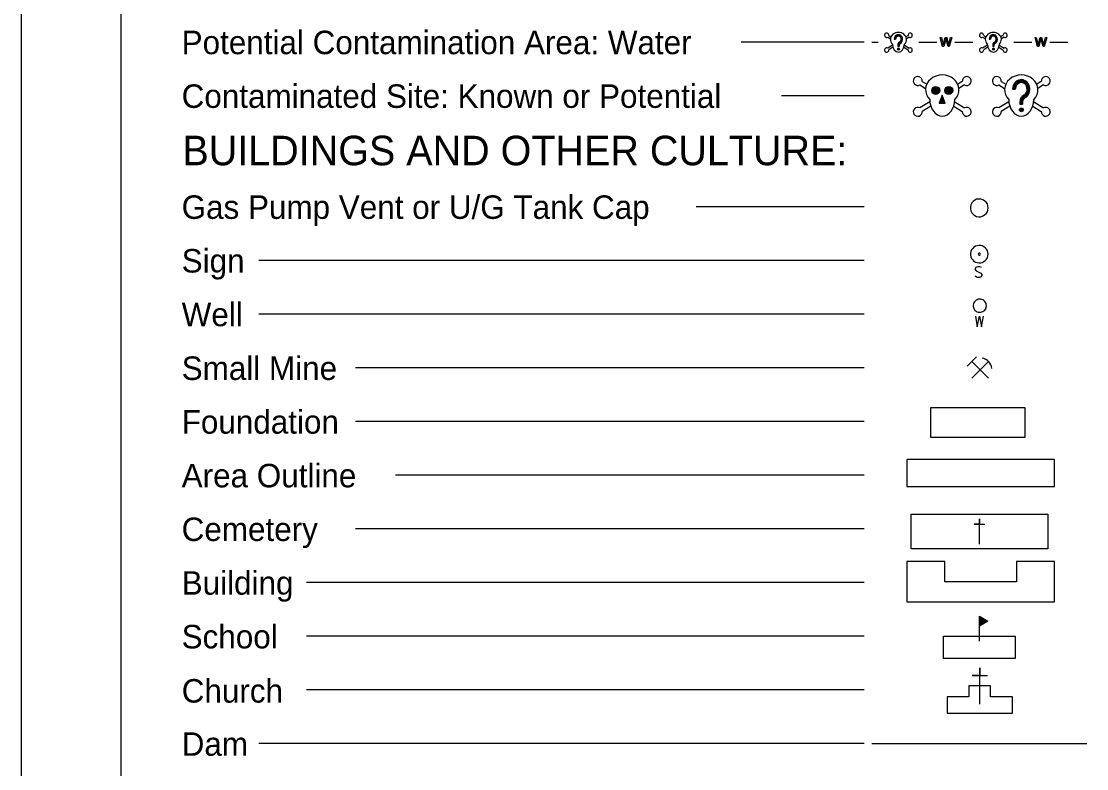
# Model space of a CAD drawing. Extents: x -0.53 to 3.34, y -0.27 to 4.33.
# Drawn here: x 0.217 to 0.885, y 2.956 to 3.424 of the extents above; entities that cross this region are included whole.
import ezdxf

# ---------------------------------------------------------------- set-up
doc = ezdxf.new("R2010")
doc.units = 0
for name, color, linetype in [('Sheet_Plan', 7, 'Continuous'), ('Sheet_Symbology', 7, 'Continuous'), ('z - Construction', 7, 'Continuous')]:
    doc.layers.add(name, color=color, linetype=linetype)

msp = doc.modelspace()

# ---------------------------------------------------------------- linework, layer by layer
at = {"layer": 'Sheet_Plan'}
msp.add_line((0.2799, 2.55761), (0.2799, 4.26594), dxfattribs=at)
at = {"layer": 'Sheet_Symbology'}
for p, q in [((0.7452, 3.41079), (0.66821, 3.41079)), ((0.75003, 3.41081), (0.75392, 3.41081)), ((0.75995, 3.41387), (0.76164, 3.41281)), ((0.76062, 3.41494), (0.76199, 3.41408)), ((0.76406, 3.41257), (0.76486, 3.41257)), ((0.76665, 3.41081), (0.76665, 3.41081)), ((0.77269, 3.41494), (0.77132, 3.41408)), ((0.77336, 3.41387), (0.77167, 3.41281)), ((0.77939, 3.41081), (0.79071, 3.41081)), ((0.80204, 3.41081), (0.81336, 3.41081)), ((0.81939, 3.41387), (0.82109, 3.41281)), ((0.82006, 3.41494), (0.82144, 3.41408)), ((0.8235, 3.41257), (0.8243, 3.41257)), ((0.8261, 3.41081), (0.8261, 3.41081)), ((0.83213, 3.41494), (0.83076, 3.41408)), ((0.8328, 3.41387), (0.83111, 3.41281)), ((0.83884, 3.41081), (0.85016, 3.41081)), ((0.86148, 3.41081), (0.8728, 3.41081)), ((0.76291, 3.40879), (0.75995, 3.40693)), ((0.76319, 3.40748), (0.76062, 3.40586)), ((0.76625, 3.40878), (0.76625, 3.40808)), ((0.76625, 3.40808), (0.76706, 3.40808)), ((0.76637, 3.40878), (0.76637, 3.40808)), ((0.76648, 3.40878), (0.76648, 3.40808)), ((0.7666, 3.40878), (0.7666, 3.40808)), ((0.76671, 3.40878), (0.76671, 3.40808)), ((0.76683, 3.40878), (0.76683, 3.40808)), ((0.76694, 3.40878), (0.76694, 3.40808)), ((0.76706, 3.40878), (0.76706, 3.40808)), ((0.77012, 3.40748), (0.77269, 3.40586)), ((0.7704, 3.40879), (0.77336, 3.40693)), ((0.82235, 3.40879), (0.81939, 3.40693)), ((0.82264, 3.40748), (0.82006, 3.40586)), ((0.8257, 3.40878), (0.8257, 3.40808)), ((0.8257, 3.40808), (0.8265, 3.40808)), ((0.82581, 3.40878), (0.82581, 3.40808)), ((0.82593, 3.40878), (0.82593, 3.40808)), ((0.82604, 3.40878), (0.82604, 3.40808)), ((0.82616, 3.40878), (0.82616, 3.40808)), ((0.82627, 3.40878), (0.82627, 3.40808)), ((0.82638, 3.40878), (0.82638, 3.40808)), ((0.8265, 3.40878), (0.8265, 3.40808)), ((0.82956, 3.40748), (0.83213, 3.40586)), ((0.82984, 3.40879), (0.8328, 3.40693)), ((0.78016, 3.38395), (0.78368, 3.38173)), ((0.78155, 3.38617), (0.78441, 3.38438)), ((0.80665, 3.38617), (0.8038, 3.38438)), ((0.80805, 3.38395), (0.80452, 3.38173)), ((0.82964, 3.38395), (0.83317, 3.38173)), ((0.83104, 3.38617), (0.83389, 3.38438)), ((0.85614, 3.38617), (0.85328, 3.38438)), ((0.85753, 3.38395), (0.85401, 3.38173)), ((0.7452, 3.37716), (0.69334, 3.37716)), ((0.7941, 3.37673), (0.7941, 3.37673)), ((0.83819, 3.38125), (0.83985, 3.38125)), ((0.84359, 3.37759), (0.84359, 3.37759)), ((0.78631, 3.37339), (0.78016, 3.36952)), ((0.78691, 3.37066), (0.78155, 3.3673)), ((0.8013, 3.37066), (0.80665, 3.3673)), ((0.80189, 3.37339), (0.80805, 3.36952)), ((0.8358, 3.37339), (0.82964, 3.36952)), ((0.83639, 3.37066), (0.83104, 3.3673)), ((0.84275, 3.37337), (0.84275, 3.3719)), ((0.84275, 3.3719), (0.84442, 3.3719)), ((0.84299, 3.37337), (0.84299, 3.3719)), ((0.84323, 3.37337), (0.84323, 3.3719)), ((0.84347, 3.37337), (0.84347, 3.3719)), ((0.84371, 3.37337), (0.84371, 3.3719)), ((0.84395, 3.37337), (0.84395, 3.3719)), ((0.84418, 3.37337), (0.84418, 3.3719)), ((0.84442, 3.37337), (0.84442, 3.3719)), ((0.85079, 3.37066), (0.85614, 3.3673)), ((0.85138, 3.37339), (0.85753, 3.36952)), ((0.7452, 3.30764), (0.63995, 3.30764)), ((0.7452, 3.27401), (0.36613, 3.27401)), ((0.7452, 3.24038), (0.36613, 3.24038)), ((0.81265, 3.21071), (0.80961, 3.20767)), ((0.81265, 3.20025), (0.82312, 3.21071)), ((0.7452, 3.20674), (0.42667, 3.20674)), ((0.81789, 3.20548), (0.81729, 3.20607)), ((0.81789, 3.20548), (0.82312, 3.20025)), ((0.78688, 3.18192), (0.84573, 3.18192)), ((0.78688, 3.16311), (0.78688, 3.18192)), ((0.84573, 3.18192), (0.84573, 3.16311)), ((0.7452, 3.17311), (0.42667, 3.17311)), ((0.84573, 3.16311), (0.78688, 3.16311)), ((0.86436, 3.14924), (0.77187, 3.14924)), ((0.77187, 3.14924), (0.77187, 3.13242)), ((0.86436, 3.13242), (0.86436, 3.14924)), ((0.7452, 3.13948), (0.45181, 3.13948)), ((0.77187, 3.13242), (0.86436, 3.13242)), ((0.77465, 3.11497), (0.86017, 3.11497)), ((0.77465, 3.09345), (0.77465, 3.11497)), ((0.86017, 3.11497), (0.86017, 3.09345)), ((0.7452, 3.10585), (0.42667, 3.10585)), ((0.86017, 3.09345), (0.77465, 3.09345)), ((0.79569, 3.0854), (0.77187, 3.0854)), ((0.77187, 3.0854), (0.77187, 3.06018)), ((0.79569, 3.07279), (0.79569, 3.0854)), ((0.86436, 3.0854), (0.84054, 3.0854)), ((0.84054, 3.0854), (0.84054, 3.07279)), ((0.86436, 3.06018), (0.86436, 3.0854)), ((0.7452, 3.07222), (0.39592, 3.07222)), ((0.84054, 3.07279), (0.79569, 3.07279)), ((0.77187, 3.06018), (0.86436, 3.06018)), ((0.7452, 3.03859), (0.39592, 3.03859)), ((0.79487, 3.03859), (0.83981, 3.03859)), ((0.79487, 3.02463), (0.79487, 3.03859)), ((0.83981, 3.03859), (0.83981, 3.02463)), ((0.83981, 3.02463), (0.79487, 3.02463)), ((0.7452, 3.00496), (0.39592, 3.00496)), ((0.82438, 3.00746), (0.81076, 3.00746)), ((0.81076, 3.00746), (0.81076, 3.00067)), ((0.82438, 3.00067), (0.82438, 3.00746)), ((0.81076, 3.00067), (0.79714, 3.00067)), ((0.79714, 3.00067), (0.79714, 2.99043)), ((0.838, 3.00067), (0.82438, 3.00067)), ((0.838, 2.99043), (0.838, 3.00067)), ((0.79714, 2.99043), (0.838, 2.99043)), ((0.7452, 2.97133), (0.36613, 2.97133)), ((0.75003, 2.97133), (0.88456, 2.97133))]:
    msp.add_line(p, q, dxfattribs=at)
for points in [[(0.79625, 3.4123), (0.79506, 3.40798), (0.79429, 3.40798), (0.79278, 3.41364), (0.79355, 3.41364), (0.79441, 3.40993)], [(0.79491, 3.40982), (0.79599, 3.41364), (0.79689, 3.41364), (0.7977, 3.41078)], [(0.79842, 3.41001), (0.79931, 3.41364), (0.80006, 3.41364), (0.79852, 3.40798), (0.79779, 3.40798), (0.7966, 3.4123)], [(0.85569, 3.4123), (0.8545, 3.40798), (0.85373, 3.40798), (0.85223, 3.41364), (0.853, 3.41364), (0.85386, 3.40993)], [(0.85435, 3.40982), (0.85543, 3.41364), (0.85633, 3.41364), (0.85715, 3.41078)], [(0.85787, 3.41001), (0.85875, 3.41364), (0.85951, 3.41364), (0.85796, 3.40798), (0.85723, 3.40798), (0.85604, 3.4123)], [(0.82294, 3.30692), (0.82264, 3.30826), (0.82234, 3.30945), (0.8216, 3.3105), (0.82055, 3.31139), (0.81951, 3.31199), (0.81832, 3.31244), (0.81697, 3.31244), (0.81563, 3.31229), (0.81444, 3.31169), (0.8134, 3.31095), (0.81266, 3.31005), (0.81206, 3.30886), (0.81176, 3.30752), (0.81176, 3.30633), (0.81206, 3.30499), (0.81266, 3.3038), (0.8134, 3.3029), (0.81444, 3.30216), (0.81563, 3.30156), (0.81697, 3.30141), (0.81832, 3.30141), (0.81951, 3.30186), (0.82055, 3.30246), (0.8216, 3.30335), (0.82234, 3.30439), (0.82264, 3.30558), (0.82294, 3.30692)], [(0.82278, 3.27791), (0.82267, 3.279), (0.82234, 3.2801), (0.82179, 3.28108), (0.82103, 3.28185), (0.82016, 3.2825), (0.81917, 3.28305), (0.81819, 3.28327), (0.81699, 3.28337), (0.8159, 3.28316), (0.81491, 3.28283), (0.81393, 3.28228), (0.81316, 3.28152), (0.81251, 3.28054), (0.81207, 3.27955), (0.81185, 3.27846), (0.81185, 3.27737), (0.81207, 3.27627), (0.81251, 3.27529), (0.81316, 3.27431), (0.81393, 3.27354), (0.81491, 3.273), (0.8159, 3.27267), (0.81699, 3.27245), (0.81819, 3.27256), (0.81917, 3.27278), (0.82016, 3.27332), (0.82103, 3.27398), (0.82179, 3.27475), (0.82234, 3.27573), (0.82267, 3.27682), (0.82278, 3.27791)], [(0.81754, 3.27857), (0.81721, 3.27857), (0.81688, 3.27835), (0.81666, 3.27802), (0.81677, 3.27769), (0.81699, 3.27737), (0.81732, 3.27726), (0.81764, 3.27737), (0.81786, 3.27759), (0.81797, 3.27802), (0.81786, 3.27835), (0.81754, 3.27857)], [(0.8186, 3.26949), (0.81754, 3.26997), (0.81632, 3.26997), (0.81521, 3.26949), (0.81473, 3.26865), (0.81473, 3.26833), (0.81526, 3.26754), (0.81833, 3.26595), (0.81886, 3.2652), (0.81881, 3.26457), (0.81833, 3.26372), (0.81743, 3.26325), (0.81616, 3.26325), (0.81558, 3.26346), (0.81473, 3.26404)], [(0.82177, 3.2456), (0.82164, 3.24633), (0.82151, 3.24706), (0.82117, 3.24772), (0.82071, 3.24832), (0.82018, 3.24885), (0.81958, 3.24925), (0.81886, 3.24951), (0.81813, 3.24971), (0.8174, 3.24971), (0.81667, 3.24964), (0.81594, 3.24938), (0.81535, 3.24905), (0.81475, 3.24858), (0.81422, 3.24805), (0.81389, 3.24739), (0.81363, 3.24673), (0.81349, 3.246), (0.81349, 3.24521), (0.81363, 3.24448), (0.81389, 3.24381), (0.81422, 3.24316), (0.81475, 3.24262), (0.81535, 3.24216), (0.81594, 3.24183), (0.81667, 3.24156), (0.8174, 3.2415), (0.81813, 3.2415), (0.81886, 3.2417), (0.81958, 3.24196), (0.82018, 3.24236), (0.82071, 3.24289), (0.82117, 3.24348), (0.82151, 3.24415), (0.82164, 3.24488), (0.82177, 3.2456)], [(0.8149, 3.23911), (0.81596, 3.23239), (0.81733, 3.23911), (0.81871, 3.23239), (0.81988, 3.23911)], [(0.81789, 3.20548), (0.81265, 3.21071), (0.81561, 3.21366)], [(0.82523, 3.20641), (0.82498, 3.20759), (0.82455, 3.20869), (0.82396, 3.2097), (0.8232, 3.21054), (0.82236, 3.21139), (0.82135, 3.21198), (0.82025, 3.21248), (0.81915, 3.21274)], [(0.81744, 3.09635), (0.81744, 3.11211), (0.81744, 3.10876), (0.81409, 3.10876), (0.82079, 3.10876)], [(0.8174, 3.03546), (0.8174, 3.05122), (0.82267, 3.04812), (0.8174, 3.04502), (0.81771, 3.04551), (0.81771, 3.05079), (0.82205, 3.04806), (0.81802, 3.0457), (0.81808, 3.05029), (0.82156, 3.04806), (0.81839, 3.04626), (0.81839, 3.04973), (0.821, 3.04806), (0.81876, 3.04681), (0.81876, 3.04917), (0.82044, 3.04812), (0.81908, 3.04731), (0.81908, 3.04861), (0.81994, 3.04812), (0.81939, 3.04781), (0.81932, 3.04818), (0.81951, 3.04812)], [(0.81757, 2.99611), (0.81757, 3.01881), (0.81757, 3.01398), (0.81274, 3.01398), (0.8224, 3.01398)]]:
    msp.add_lwpolyline(points, dxfattribs=at)
for points in [[(0.7941, 3.37759), (0.79226, 3.37255), (0.79595, 3.37255)], [(0.7941, 3.37673), (0.79268, 3.37285), (0.79553, 3.37285)], [(0.7941, 3.37588), (0.7931, 3.37314), (0.79511, 3.37314)], [(0.7941, 3.37502), (0.79352, 3.37343), (0.79468, 3.37343)], [(0.7941, 3.37417), (0.79394, 3.37373), (0.79426, 3.37373)]]:
    msp.add_lwpolyline(points, close=True, dxfattribs=at)
for centre, radius in [((0.76668, 3.40633), 0.000573), ((0.76668, 3.40633), 0.000446), ((0.76668, 3.40633), 0.000316), ((0.76668, 3.40633), 0.000188), ((0.76668, 3.40633), 0.0000611), ((0.82613, 3.40633), 0.000573), ((0.82613, 3.40633), 0.000446), ((0.82613, 3.40633), 0.000316), ((0.82613, 3.40633), 0.000188), ((0.82613, 3.40633), 0.0000611), ((0.79005, 3.38045), 0.0025), ((0.79005, 3.38045), 0.0022), ((0.79816, 3.38045), 0.0025), ((0.79816, 3.38045), 0.0022), ((0.79005, 3.38045), 0.00191), ((0.79005, 3.38045), 0.00161), ((0.79005, 3.38045), 0.00132), ((0.79005, 3.38045), 0.00102), ((0.79005, 3.38045), 0.00073), ((0.79005, 3.38045), 0.000435), ((0.79005, 3.38045), 0.000141), ((0.79816, 3.38045), 0.00191), ((0.79816, 3.38045), 0.00161), ((0.79816, 3.38045), 0.00132), ((0.79816, 3.38045), 0.00102), ((0.79816, 3.38045), 0.00073), ((0.79816, 3.38045), 0.000435), ((0.79816, 3.38045), 0.000141), ((0.84365, 3.36828), 0.00119), ((0.84365, 3.36828), 0.000927), ((0.84365, 3.36828), 0.000657), ((0.84365, 3.36828), 0.000392), ((0.84365, 3.36828), 0.000127)]:
    msp.add_circle(centre, radius, dxfattribs=at)
for centre, radius, start, end in [((0.75928, 3.41504), 0.00134, 355.89762, 299.80617), ((0.77403, 3.41504), 0.00134, 240.19383, 184.10238), ((0.81872, 3.41504), 0.00134, 355.89762, 299.80617), ((0.83347, 3.41504), 0.00134, 240.19383, 184.10238), ((0.75928, 3.40577), 0.00134, 60.19383, 4.10238), ((0.77403, 3.40577), 0.00134, 175.89762, 119.80617), ((0.81872, 3.40577), 0.00134, 60.19383, 4.10238), ((0.83347, 3.40577), 0.00134, 175.89762, 119.80617), ((0.77877, 3.38637), 0.00279, 355.89762, 299.80617), ((0.80943, 3.38637), 0.00279, 240.19383, 184.10238), ((0.82826, 3.38637), 0.00279, 355.89762, 299.80617), ((0.85892, 3.38637), 0.00279, 240.19383, 184.10238), ((0.77877, 3.3671), 0.00279, 60.19383, 4.10238), ((0.80943, 3.3671), 0.00279, 175.89762, 119.80617), ((0.82826, 3.3671), 0.00279, 60.19383, 4.10238), ((0.85892, 3.3671), 0.00279, 175.89762, 119.80617)]:
    msp.add_arc(centre, radius, start, end, dxfattribs=at)
for centre, major_axis, ratio, start_param, end_param in [((0.76665, 3.4124), (0.00503, 0), 0.885014, 5.564242, 10.143721), ((0.8261, 3.4124), (0.00503, 0), 0.885014, 5.564242, 10.143721), ((0.76665, 3.40952), (0, -0.00503), 0.752542, 4.722735, 7.843636), ((0.76665, 3.41257), (0, 0.00289), 0.9, 3.567618, 7.853982), ((0.76665, 3.41257), (0, 0.00276), 0.9, 3.567618, 7.853982), ((0.76665, 3.41257), (0, 0.00263), 0.9, 3.567618, 7.853982), ((0.76665, 3.41257), (0, 0.00251), 0.9, 3.567618, 7.853982), ((0.76665, 3.41257), (0, 0.00238), 0.9, 3.567618, 7.853982), ((0.76665, 3.41257), (0, 0.00225), 0.9, 3.567618, 7.853982), ((0.76665, 3.41257), (0, 0.00212), 0.9, 3.567618, 7.853982), ((0.76665, 3.41257), (0, 0.002), 0.9, 3.567618, 7.853982), ((0.7682, 3.40878), (0, 0.00217), 0.9, 0.426026, 1.570796), ((0.7682, 3.40878), (0, 0.00204), 0.9, 0.426026, 1.570796), ((0.7682, 3.40878), (0, 0.00191), 0.9, 0.426026, 1.570796), ((0.7682, 3.40878), (0, 0.00178), 0.9, 0.426026, 1.570796), ((0.7682, 3.40878), (0, 0.00166), 0.9, 0.426026, 1.570796), ((0.7682, 3.40878), (0, 0.00153), 0.9, 0.426026, 1.570796), ((0.7682, 3.40878), (0, 0.0014), 0.9, 0.426026, 1.570796), ((0.7682, 3.40878), (0, 0.00127), 0.9, 0.426026, 1.570796), ((0.8261, 3.40952), (0, -0.00503), 0.752542, 4.722735, 7.843636), ((0.8261, 3.41257), (0, 0.00289), 0.9, 3.567618, 7.853982), ((0.8261, 3.41257), (0, 0.00276), 0.9, 3.567618, 7.853982), ((0.8261, 3.41257), (0, 0.00263), 0.9, 3.567618, 7.853982), ((0.8261, 3.41257), (0, 0.00251), 0.9, 3.567618, 7.853982), ((0.8261, 3.41257), (0, 0.00238), 0.9, 3.567618, 7.853982), ((0.8261, 3.41257), (0, 0.00225), 0.9, 3.567618, 7.853982), ((0.8261, 3.41257), (0, 0.00212), 0.9, 3.567618, 7.853982), ((0.8261, 3.41257), (0, 0.002), 0.9, 3.567618, 7.853982), ((0.82765, 3.40878), (0, 0.00217), 0.9, 0.426026, 1.570796), ((0.82765, 3.40878), (0, 0.00204), 0.9, 0.426026, 1.570796), ((0.82765, 3.40878), (0, 0.00191), 0.9, 0.426026, 1.570796), ((0.82765, 3.40878), (0, 0.00178), 0.9, 0.426026, 1.570796), ((0.82765, 3.40878), (0, 0.00166), 0.9, 0.426026, 1.570796), ((0.82765, 3.40878), (0, 0.00153), 0.9, 0.426026, 1.570796), ((0.82765, 3.40878), (0, 0.0014), 0.9, 0.426026, 1.570796), ((0.82765, 3.40878), (0, 0.00127), 0.9, 0.426026, 1.570796), ((0.7941, 3.3809), (0.01046, 0), 0.885014, 5.564242, 10.143721), ((0.84359, 3.3809), (0.01046, 0), 0.885014, 5.564242, 10.143721), ((0.84359, 3.38125), (0, 0.006), 0.9, 3.567618, 7.853982), ((0.84359, 3.38125), (0, 0.00574), 0.9, 3.567618, 7.853982), ((0.84359, 3.38125), (0, 0.00547), 0.9, 3.567618, 7.853982), ((0.84359, 3.38125), (0, 0.00521), 0.9, 3.567618, 7.853982), ((0.84359, 3.38125), (0, 0.00494), 0.9, 3.567618, 7.853982), ((0.84359, 3.38125), (0, 0.00468), 0.9, 3.567618, 7.853982), ((0.84359, 3.38125), (0, 0.00441), 0.9, 3.567618, 7.853982), ((0.84359, 3.38125), (0, 0.00415), 0.9, 3.567618, 7.853982), ((0.84681, 3.37337), (0, 0.0045), 0.9, 0.426026, 1.570796), ((0.84681, 3.37337), (0, 0.00424), 0.9, 0.426026, 1.570796), ((0.84681, 3.37337), (0, 0.00397), 0.9, 0.426026, 1.570796), ((0.84681, 3.37337), (0, 0.00371), 0.9, 0.426026, 1.570796), ((0.84681, 3.37337), (0, 0.00344), 0.9, 0.426026, 1.570796), ((0.84681, 3.37337), (0, 0.00318), 0.9, 0.426026, 1.570796), ((0.84681, 3.37337), (0, 0.00291), 0.9, 0.426026, 1.570796), ((0.7941, 3.37491), (0, -0.01046), 0.752542, 4.722735, 7.843636), ((0.84359, 3.37491), (0, -0.01046), 0.752542, 4.722735, 7.843636), ((0.84681, 3.37337), (0, 0.00265), 0.9, 0.426026, 1.570796)]:
    msp.add_ellipse(centre, major_axis=major_axis, ratio=ratio, start_param=start_param, end_param=end_param, dxfattribs=at)
for points in [[(0.79441, 3.40993), (0.79456, 3.40935), (0.79465, 3.40877)], [(0.79465, 3.40877), (0.79487, 3.40968), (0.79491, 3.40982)], [(0.79642, 3.41296), (0.79633, 3.41257), (0.79625, 3.4123)], [(0.7966, 3.4123), (0.79645, 3.41284), (0.79642, 3.41296)], [(0.7977, 3.41078), (0.798, 3.40971), (0.79814, 3.40877)], [(0.79814, 3.40877), (0.79825, 3.40931), (0.79842, 3.41001)], [(0.85386, 3.40993), (0.854, 3.40935), (0.8541, 3.40877)], [(0.8541, 3.40877), (0.85431, 3.40968), (0.85435, 3.40982)], [(0.85586, 3.41296), (0.85577, 3.41257), (0.85569, 3.4123)], [(0.85604, 3.4123), (0.85589, 3.41284), (0.85586, 3.41296)], [(0.85715, 3.41078), (0.85745, 3.40971), (0.85758, 3.40877)], [(0.85758, 3.40877), (0.8577, 3.40931), (0.85787, 3.41001)]]:
    msp.add_open_spline(points, degree=2, dxfattribs=at)
at = {"layer": 'z - Construction'}
msp.add_line((0.2174, 4.32844), (0.2174, 2.49511), dxfattribs=at)

# ---------------------------------------------------------------- texts
at = {"layer": 'Sheet_Symbology'}
for s, height, p in [('Potential Contamination Area: Water', 0.0147137, (0.31781, 3.40318)), ('Contaminated Site: Known or Potential', 0.0147137, (0.31781, 3.36955)), ('BUILDINGS AND OTHER CULTURE:', 0.0184972, (0.31827, 3.33362)), ('Gas Pump Vent or U/G Tank Cap', 0.0147137, (0.31781, 3.30003)), ('Sign', 0.014714, (0.31783, 3.26642)), ('Well', 0.014714, (0.31783, 3.23279)), ('Small Mine', 0.014714, (0.31783, 3.19914)), ('Foundation', 0.014714, (0.31783, 3.1655)), ('Area Outline', 0.0147137, (0.31783, 3.13187)), ('Cemetery', 0.014714, (0.31781, 3.09826)), ('Building', 0.014714, (0.31783, 3.06463)), ('School', 0.014714, (0.31781, 3.031)), ('Church', 0.014714, (0.31785, 2.99705)), ('Dam', 0.014714, (0.31783, 2.96374))]:
    msp.add_text(s, height=height, dxfattribs=at).set_placement(p)

doc.saveas('drawing.dxf')
